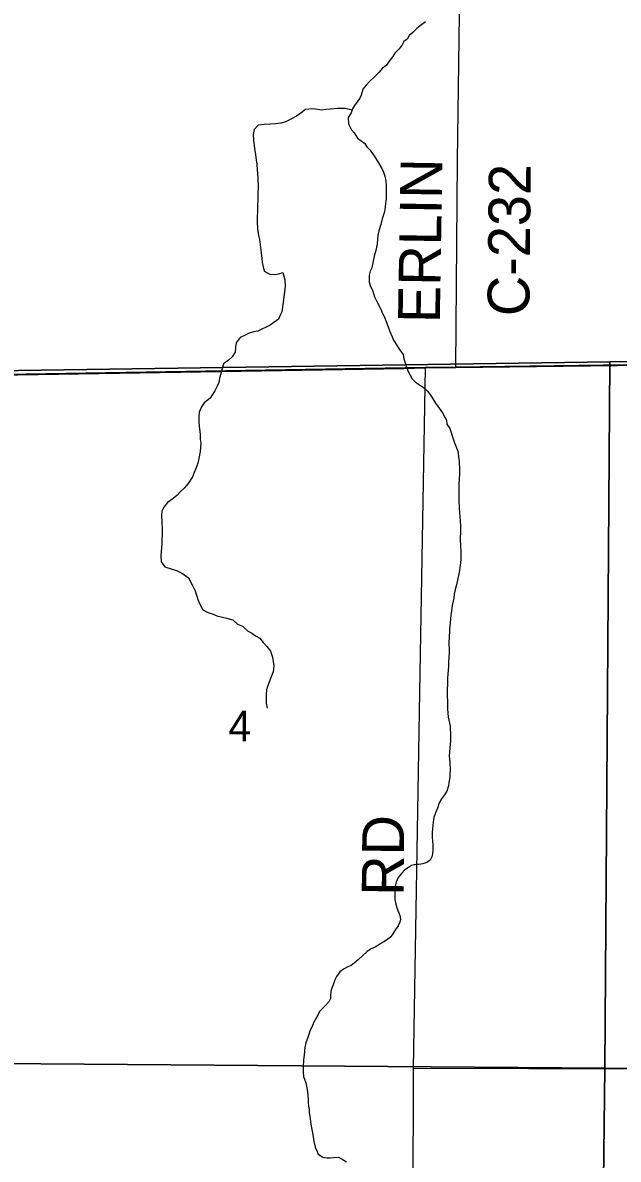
# Model space of a CAD drawing. Extents: x 36.7 to 70.7, y 0 to 22.
# Drawn here: x 43.478 to 44.287, y 18.785 to 20.33 of the extents above; entities that cross this region are included whole.
import ezdxf

# ---------------------------------------------------------------- set-up
doc = ezdxf.new("R2010")
doc.units = 0
for name, color, linetype in [('GM_X_County_Road', 7, 'Continuous'), ('GM_X_County_Road_Text', 7, 'Continuous'), ('GM_X_Minor_River', 7, 'Continuous'), ('GM_X_Section', 7, 'Continuous'), ('GM_X_Section_Text', 7, 'Continuous'), ('GM_X_Township_Road', 7, 'Continuous')]:
    doc.layers.add(name, color=color, linetype=linetype)

msp = doc.modelspace()

# ---------------------------------------------------------------- linework, layer by layer
at = {"layer": 'GM_X_County_Road'}
for p, q in [((43.3192, 19.8488), (43.9954, 19.8602)), ((43.9954, 19.8602), (44.0248, 19.8607)), ((44.0173, 19.4198), (44.0248, 19.8607)), ((44.0248, 19.8607), (44.0658, 19.8612)), ((44.0658, 19.8612), (44.5269, 19.8674))]:
    msp.add_line(p, q, dxfattribs=at)
for points in [[(44.0658, 19.8612), (44.0684, 20.1426), (44.0712, 20.3408), (44.0721, 20.3499), (44.0725, 20.3518), (44.0729, 20.3545), (44.0741, 20.3564), (44.0776, 20.3613), (44.0799, 20.3631), (44.2998, 20.3691), (44.3207, 20.3695), (44.3292, 20.8716), (44.3295, 20.8969)], [(44.0037, 18.4362), (44.004, 18.445), (44.0053, 18.5319), (44.0064, 18.6321), (44.0077, 18.7436), (44.0085, 18.8412), (44.0087, 18.9088), (44.0173, 19.4198)]]:
    msp.add_lwpolyline(points, dxfattribs=at)
at = {"layer": 'GM_X_Minor_River'}
for points in [[(44.0246, 20.3314), (44.0174, 20.3258), (44.0131, 20.3224), (44.0074, 20.3168), (44.0028, 20.3126), (44.0001, 20.3077), (43.9955, 20.3044), (43.9932, 20.2998), (43.9889, 20.2946), (43.9832, 20.2889), (43.9805, 20.284), (43.9766, 20.2795), (43.9712, 20.272), (43.9666, 20.2682), (43.9612, 20.2626), (43.9551, 20.2562), (43.9494, 20.2506), (43.9444, 20.2453), (43.9397, 20.2397), (43.9374, 20.2317), (43.9354, 20.2276), (43.9285, 20.2174), (43.9258, 20.2129), (43.9238, 20.2076), (43.9196, 20.2012), (43.9202, 20.1928), (43.9243, 20.1844), (43.9281, 20.1802), (43.9325, 20.1733), (43.9423, 20.166), (43.9449, 20.1614), (43.949, 20.1572), (43.9543, 20.1503), (43.9595, 20.1419), (43.9654, 20.132), (43.9677, 20.127), (43.9695, 20.1213), (43.9709, 20.1152), (43.9716, 20.108), (43.9714, 20.0917), (43.971, 20.0875), (43.9702, 20.0803), (43.9694, 20.0757), (43.9682, 20.0704), (43.9658, 20.0633), (43.9642, 20.0557), (43.9614, 20.047), (43.9602, 20.0409), (43.9598, 20.036), (43.959, 20.0295), (43.9573, 20.0204), (43.955, 20.0129), (43.9542, 20.008), (43.953, 20.0015), (43.9518, 19.997), (43.9498, 19.9924), (43.9482, 19.9871), (43.9485, 19.9773), (43.9503, 19.9716), (43.9529, 19.9666), (43.9555, 19.9575), (43.9588, 19.9513), (43.964, 19.9407), (43.9666, 19.9349), (43.9696, 19.9288), (43.9729, 19.9204), (43.9747, 19.9151), (43.9762, 19.9105), (43.9795, 19.9029), (43.9814, 19.8983), (43.9903, 19.8846), (43.9944, 19.8792), (43.9955, 19.8731), (43.9977, 19.8663), (43.9988, 19.8617), (44.0006, 19.8567), (44.0066, 19.8461), (44.0111, 19.8415), (44.0178, 19.8368), (44.0235, 19.8333), (44.0276, 19.8291), (44.0306, 19.8249), (44.0343, 19.8196), (44.0384, 19.8127), (44.0433, 19.8062), (44.0478, 19.7997), (44.0511, 19.794), (44.0533, 19.7898), (44.054, 19.7844), (44.0578, 19.7783), (44.0625, 19.7646), (44.064, 19.7589), (44.0658, 19.7543)], [(43.9252, 20.2113), (43.9155, 20.2134), (43.9049, 20.2135), (43.8951, 20.2124), (43.8897, 20.2121), (43.884, 20.2114), (43.8784, 20.2122), (43.8712, 20.2131), (43.8617, 20.212), (43.8555, 20.2072), (43.8494, 20.2031), (43.8429, 20.1993), (43.8353, 20.1952), (43.8281, 20.1934), (43.8212, 20.1927), (43.8136, 20.1921), (43.806, 20.1918), (43.7977, 20.1907), (43.7923, 20.1847), (43.7907, 20.1779), (43.791, 20.1703), (43.7924, 20.1589), (43.7938, 20.1505), (43.7949, 20.1437), (43.7956, 20.138), (43.7962, 20.13), (43.7969, 20.1197), (43.7975, 20.1057), (43.797, 20.0988), (43.7969, 20.0897), (43.7964, 20.0806), (43.7962, 20.0598), (43.7968, 20.0495), (43.7979, 20.0408), (43.7993, 20.0354), (43.8004, 20.0282), (43.8014, 20.0172), (43.8025, 20.0096), (43.8031, 20.0039), (43.8042, 19.9982), (43.8057, 19.9925), (43.8132, 19.9882), (43.8193, 19.9878), (43.8257, 19.9888), (43.8311, 19.9903), (43.8336, 19.9804), (43.8343, 19.972), (43.8326, 19.9569), (43.8297, 19.9372), (43.8274, 19.9323), (43.825, 19.927), (43.8189, 19.9225), (43.8139, 19.9191), (43.7972, 19.9109), (43.7911, 19.9099), (43.7854, 19.908), (43.78, 19.9054), (43.7732, 19.9021), (43.7678, 19.8949), (43.7669, 19.8892), (43.7661, 19.8824), (43.7622, 19.876), (43.7569, 19.8708), (43.7504, 19.8663), (43.7468, 19.8526), (43.7452, 19.847), (43.744, 19.8409), (43.7417, 19.836), (43.7386, 19.8296), (43.7324, 19.8198), (43.7244, 19.8134), (43.7205, 19.8081), (43.7174, 19.8006), (43.7169, 19.7941), (43.7169, 19.788), (43.7172, 19.7812), (43.7186, 19.7709), (43.7189, 19.7641), (43.7195, 19.7584), (43.7187, 19.747), (43.717, 19.7376), (43.7158, 19.7311), (43.7127, 19.7239), (43.7104, 19.7186), (43.7084, 19.7126), (43.7026, 19.7035), (43.6969, 19.6975), (43.6915, 19.6923), (43.6869, 19.6874), (43.6819, 19.6833), (43.6746, 19.678), (43.6692, 19.6716), (43.6665, 19.666), (43.6661, 19.6595), (43.6667, 19.6519), (43.667, 19.6413), (43.6668, 19.6216), (43.6655, 19.6056), (43.6657, 19.5973), (43.6706, 19.5904), (43.6808, 19.5872)], [(44.0658, 19.7543), (44.0688, 19.7478), (44.0698, 19.7398), (44.0705, 19.7334), (44.0712, 19.7224), (44.0711, 19.7167), (44.0706, 19.7098), (44.0702, 19.7034), (44.07, 19.6863), (44.0703, 19.6795), (44.0706, 19.6704), (44.0712, 19.6632), (44.0716, 19.6586), (44.0719, 19.6525), (44.0722, 19.6461), (44.0725, 19.6388), (44.072, 19.6278), (44.0723, 19.6183), (44.0726, 19.6119), (44.0729, 19.607), (44.0728, 19.6013), (44.0724, 19.5952), (44.0715, 19.5899), (44.0711, 19.5853), (44.0703, 19.5808), (44.0667, 19.566), (44.0655, 19.5615), (44.0647, 19.5573), (44.0639, 19.5531), (44.0631, 19.5482), (44.0623, 19.5437), (44.0611, 19.538), (44.0602, 19.53), (44.0594, 19.5255), (44.0586, 19.5194), (44.0582, 19.5149), (44.0577, 19.5099), (44.0573, 19.5054), (44.0573, 19.5012), (44.0568, 19.497), (44.0567, 19.4849), (44.057, 19.4784), (44.0569, 19.4727), (44.0565, 19.4674), (44.056, 19.4606), (44.056, 19.4553), (44.0551, 19.4439), (44.0547, 19.4394), (44.0544, 19.4147), (44.0547, 19.4079), (44.0546, 19.3972), (44.0556, 19.3858), (44.0574, 19.3778), (44.0581, 19.3737), (44.0587, 19.36), (44.0586, 19.3535), (44.0578, 19.3448), (44.0573, 19.3384), (44.0569, 19.3334), (44.0576, 19.3289), (44.0579, 19.3247), (44.0582, 19.3141), (44.0577, 19.308), (44.0577, 19.3038), (44.0564, 19.297), (44.056, 19.2928), (44.0537, 19.2853), (44.0506, 19.2804), (44.0467, 19.2751), (44.0432, 19.2694), (44.0409, 19.2622), (44.0385, 19.2558), (44.0362, 19.2498), (44.0353, 19.2433), (44.0337, 19.2297), (44.034, 19.2228), (44.0346, 19.2118), (44.0349, 19.2057), (44.0345, 19.2004), (44.0333, 19.1959), (44.031, 19.1914), (44.0264, 19.1884), (44.0214, 19.1865), (44.0157, 19.1858), (44.0116, 19.1859), (44.0058, 19.1844), (44.0016, 19.1818), (43.9967, 19.1784), (43.9921, 19.1736), (43.9878, 19.1679), (43.9851, 19.1619), (43.9835, 19.1562), (43.9831, 19.1486), (43.983, 19.1437), (43.9833, 19.138), (43.9844, 19.1319), (43.9858, 19.1269), (43.988, 19.1208), (43.9899, 19.1163), (43.991, 19.1113), (43.9898, 19.1071)], [(43.6808, 19.5872), (43.6876, 19.5849), (43.6948, 19.5814), (43.7027, 19.5756), (43.7079, 19.5657), (43.712, 19.5577), (43.7156, 19.5459), (43.7186, 19.5386), (43.7223, 19.5321), (43.7283, 19.5287), (43.7366, 19.5259), (43.7415, 19.5236), (43.7548, 19.5204), (43.7631, 19.5184), (43.7695, 19.5126), (43.7763, 19.5095), (43.783, 19.5034), (43.7887, 19.5003), (43.7939, 19.4964), (43.8, 19.4933), (43.8041, 19.4876), (43.8093, 19.4822), (43.8142, 19.4757), (43.8168, 19.4677), (43.8189, 19.4556), (43.8177, 19.4476), (43.8145, 19.4385), (43.8126, 19.4336), (43.8102, 19.4279), (43.809, 19.423), (43.8086, 19.4169), (43.8085, 19.4052), (43.8097, 19.3983)], [(43.9898, 19.1071), (43.9875, 19.1022), (43.984, 19.0973), (43.9805, 19.0913), (43.9767, 19.0864), (43.9705, 19.0819), (43.9652, 19.0786), (43.9564, 19.0733), (43.9499, 19.0704), (43.9457, 19.0674), (43.9392, 19.0614), (43.9338, 19.0565), (43.9281, 19.0516), (43.9239, 19.0486), (43.9193, 19.0464), (43.9136, 19.0434), (43.9086, 19.0397), (43.904, 19.0333), (43.9016, 19.0291), (43.8993, 19.022), (43.8969, 19.0151), (43.8957, 19.0079), (43.8957, 19.0034), (43.8933, 18.9989), (43.8876, 18.9928), (43.8814, 18.9861), (43.8768, 18.9778), (43.8729, 18.9706), (43.871, 18.9653), (43.8682, 18.9604), (43.8655, 18.9517), (43.8624, 18.9434), (43.8608, 18.937), (43.8599, 18.9267), (43.8591, 18.9203), (43.8586, 18.9104), (43.8585, 18.9028), (43.8592, 18.8975), (43.8621, 18.8887), (43.8643, 18.8796), (43.865, 18.872), (43.8653, 18.8659), (43.8656, 18.8617), (43.8659, 18.8572), (43.8666, 18.8526), (43.867, 18.8481), (43.8677, 18.8435), (43.8691, 18.8329), (43.8705, 18.8253), (43.8716, 18.8188), (43.8733, 18.8093), (43.8748, 18.8013), (43.877, 18.7963), (43.8788, 18.7921), (43.8852, 18.7879), (43.8909, 18.7871), (43.8955, 18.787), (43.9, 18.7874), (43.9065, 18.7877), (43.9114, 18.7853), (43.9174, 18.7815)]]:
    msp.add_lwpolyline(points, dxfattribs=at)
at = {"layer": 'GM_X_Section'}
for points in [[(44.3293, 20.877), (44.3136, 19.8697), (44.2753, 19.8692), (43.3171, 19.855), (43.3259, 20.8559)], [(45.2759, 19.881), (45.2652, 18.9013), (44.2682, 18.9088), (44.2753, 19.8692), (44.3136, 19.8697)], [(44.2753, 19.8692), (44.2682, 18.9088), (43.2658, 18.9165), (43.2807, 19.8534), (43.3171, 19.855)], [(44.2682, 18.9088), (44.2567, 17.9094), (43.2576, 17.9081), (43.2658, 18.9165)], [(45.2652, 18.9013), (45.2484, 17.9213), (44.2567, 17.9094), (44.2682, 18.9088)]]:
    msp.add_lwpolyline(points, close=True, dxfattribs=at)
at = {"layer": 'GM_X_Township_Road'}
msp.add_line((44.0087, 18.9088), (44.5054, 18.9076), dxfattribs=at)
for points in [[(43.3189, 19.8494), (44.0245, 19.8612), (44.0656, 19.8618), (45.2722, 19.8781), (45.2981, 19.8785), (45.5934, 19.8832), (45.5934, 20.8969), (41.3748, 20.8969)], [(45.5934, 14.0969), (45.5934, 19.8832), (45.2981, 19.8785), (45.2722, 19.8781), (44.0656, 19.8618), (44.0245, 19.8612), (43.3189, 19.8494)]]:
    msp.add_lwpolyline(points, dxfattribs=at)

# ---------------------------------------------------------------- texts
at = {"layer": 'GM_X_County_Road_Text'}
for s, rotation, p in [('ERLIN', 89.0651, (44.0442, 19.9214)), ('C-232', 89.4494, (44.1658, 19.9309)), ('RD', 89.5063, (43.995, 19.1429))]:
    msp.add_text(s, height=0.05682, rotation=rotation, dxfattribs=at).set_placement(p)
at = {"layer": 'GM_X_Section_Text'}
msp.add_text('4', height=0.0419, rotation=0, dxfattribs=at).set_placement((43.7571, 19.353))

doc.saveas('drawing.dxf')
